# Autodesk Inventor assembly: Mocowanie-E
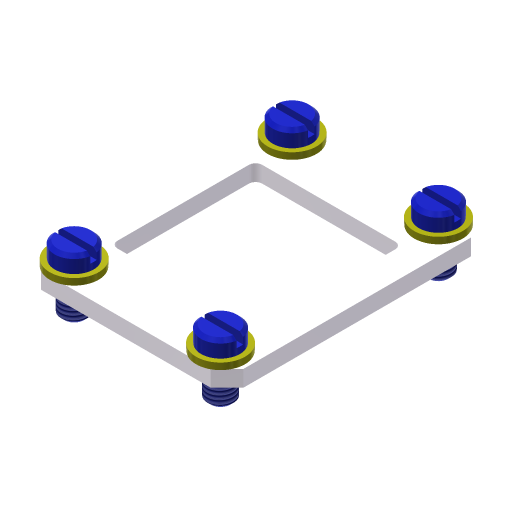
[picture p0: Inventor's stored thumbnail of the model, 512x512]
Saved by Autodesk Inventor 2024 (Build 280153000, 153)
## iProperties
Company: ATC
Created: 2023-03
Part Number: Mocowanie-E
Document SubType Name: Assembly
Designer: Andrzej Jaskulski
Stock Number: Mocowanie-E
Checked By: A.J.
Engr Approved By: Andrzej Jaskulski
Mfg Approved By: Andrzej Jaskulski
Authority: A.J.
Title: A.J.: Kurs R2024-MEP
Author: Andrzej Jaskulski
Revision Number: 1/24
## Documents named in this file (4)
- C:\Users\AndJas\Documents\R2024-MEP\Obszar roboczy\Mocowanie-E.iam
- C:\Users\AndJas\Documents\R2024-MEP\Obszar roboczy\POD.ipt
- C:\Users\AndJas\Documents\R2024-MEP\Obszar roboczy\W.ipt
- C:\Users\AndJas\Documents\R2024-MEP\Obszar roboczy\PG.ipt
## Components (9 placed, 3 different names)
1. PG:1 — Wstaw:5, Wstaw:6, Wstaw:7, Wstaw:8
2. POD:1 — Wstaw:5
3. POD:2 — Wstaw:6
4. POD:3 — Wstaw:8
5. POD:4 — Wstaw:7
6. W:1
7. W:2
8. W:3
9. W:4
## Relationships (4: Insert 4)
- Wstaw:5 [Insert]: PG:1 ↔ POD:1
- Wstaw:6 [Insert]: PG:1 ↔ POD:2
- Wstaw:7 [Insert]: PG:1 ↔ POD:4
- Wstaw:8 [Insert]: PG:1 ↔ POD:3
